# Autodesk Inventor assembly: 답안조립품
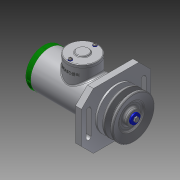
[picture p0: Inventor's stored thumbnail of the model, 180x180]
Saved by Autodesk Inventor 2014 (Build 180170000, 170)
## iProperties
Created: 2017-10
Part Number: 답안조립품
Document SubType Name: Assembly
Designer: net
Author: net
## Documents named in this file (20)
- C:\Users\net\Desktop\답안조립품.iam
- C:\Users\net\Desktop\본체.ipt
- C:\Users\net\Desktop\사이드 커버.ipt
- 사이드 커버.ipt
- C:\Users\net\Desktop\축.ipt
- C:\Users\net\Desktop\멈춤링 15 x 1.ipt
- C:\Users\net\Desktop\멈춤링 35x1.6.ipt
- C:\Users\net\Desktop\베어링 15 x 35 x 11.ipt
- C:\Users\net\Desktop\부시1.ipt
- C:\Users\net\Desktop\부시2.ipt
- C:\Users\net\Desktop\와셔 10x21.ipt
- C:\Users\net\Desktop\너트 M10.ipt
- C:\Users\net\Desktop\오일 실 15 25 7.ipt
- C:\Users\net\Desktop\키 4 x 4 x 18.ipt
- C:\Users\net\Desktop\V-벨트풀리.ipt
- C:\Users\net\Desktop\와셔 4x16.ipt
- C:\Users\net\Desktop\볼트 M4 x 10.ipt
- C:\Users\net\Desktop\탑 커버.ipt
- C:\Users\net\Desktop\와셔 3x6.ipt
- C:\Users\net\Desktop\십자볼트 M3 x 10.ipt
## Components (2 placed, 2 different names)
1. V-벨트풀리:1
2. ISO 4017 M4 x 10:1
